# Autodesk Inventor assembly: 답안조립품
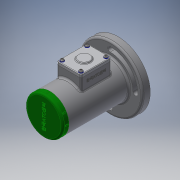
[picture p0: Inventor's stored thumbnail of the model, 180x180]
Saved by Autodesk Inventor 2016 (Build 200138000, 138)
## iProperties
Created: 2017-05
Part Number: 답안조립품
Material: 일반
Document SubType Name: Assembly
Designer: USER
Author: USER
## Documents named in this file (16)
- C:\Users\USER\Desktop\470508V1004\답안조립품.iam
- C:\Users\USER\Desktop\470508V1004\본체.ipt
- C:\Users\USER\Desktop\470508V1004\사이드 커버.ipt
- 사이드 커버.ipt
- C:\Users\USER\Desktop\470508V1004\축.ipt
- C:\Users\USER\Desktop\470508V1004\베어링 15 x 35 x 11.ipt
- C:\Users\USER\Desktop\470508V1004\부시1.ipt
- C:\Users\USER\Desktop\470508V1004\부시2.ipt
- C:\Users\USER\Desktop\470508V1004\멈춤링 35x1.6.ipt
- C:\Users\USER\Desktop\470508V1004\와셔 10x21.ipt
- C:\Users\USER\Desktop\470508V1004\너트 M10.ipt
- C:\Users\USER\Desktop\470508V1004\멈춤링 15 x 1.ipt
- C:\Users\USER\Desktop\470508V1004\오일 실 15 25 7.ipt
- C:\Users\USER\Desktop\470508V1004\탑 커버.ipt
- C:\Users\USER\Desktop\470508V1004\십자볼트 M3 x 10.ipt
- C:\Users\USER\Desktop\470508V1004\와셔 3x6.ipt
## Named parameters: d20_d19 = 0, d21_d19 = 0, d22_d19 = 0
